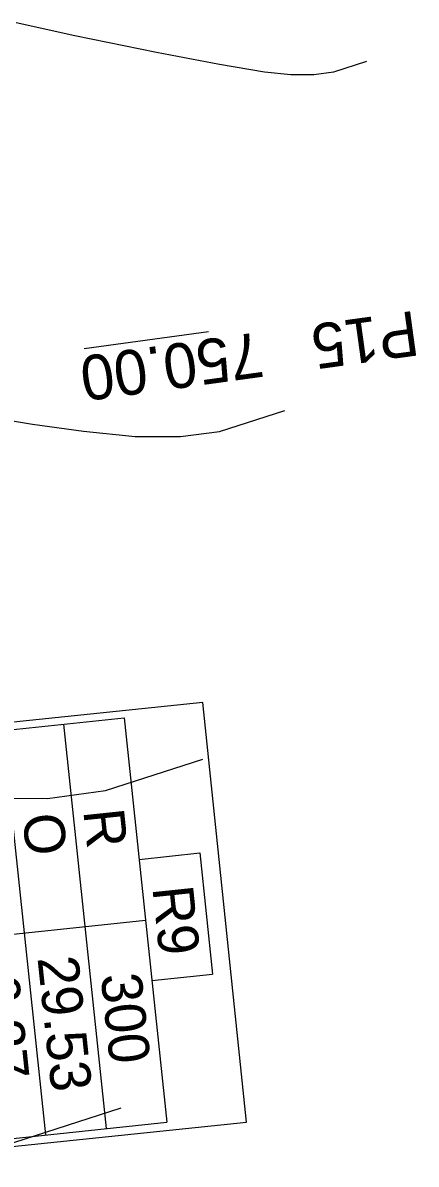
# Model space of a CAD drawing. Extents: x -574342 to -507939, y -1144044 to -1123894.
# Drawn here: x -508524.7 to -508502.7, y -1143810.6 to -1143746.9 of the extents above; entities that cross this region are included whole.
import ezdxf

# ---------------------------------------------------------------- set-up
doc = ezdxf.new("R2010")
doc.units = 0
for name, color, linetype in [('19', 7, 'Continuous'), ('6', 7, 'Continuous'), ('SO 101_popis oblouku', 7, 'Continuous'), ('VRST HL', 7, 'Continuous'), ('VRST VEDL', 7, 'Continuous')]:
    doc.layers.add(name, color=color, linetype=linetype)

msp = doc.modelspace()

# ---------------------------------------------------------------- linework, layer by layer
msp.add_lwpolyline([(-508536.292, -1143787.057), (-508533.867, -1143810.452), (-508512.21, -1143808.207), (-508514.636, -1143784.812)], close=True)
at = {"layer": '6'}
msp.add_lwpolyline([(-508514.323, -1143764.137), (-508521.258, -1143765.091)], dxfattribs=at)
at = {"layer": 'SO 101_popis oblouku'}
for p, q in [((-508535.931, -1143787.457), (-508519.025, -1143785.668)), ((-508519.025, -1143785.668), (-508516.64, -1143808.209)), ((-508525.787, -1143786.384), (-508523.403, -1143808.925)), ((-508522.406, -1143786.026), (-508520.022, -1143808.567)), ((-508518.19, -1143793.558), (-508514.809, -1143793.2)), ((-508514.809, -1143793.2), (-508514.094, -1143799.962)), ((-508534.738, -1143798.727), (-508517.833, -1143796.939)), ((-508517.475, -1143800.32), (-508514.094, -1143799.962)), ((-508533.546, -1143809.998), (-508516.64, -1143808.209))]:
    msp.add_line(p, q, dxfattribs=at)
at = {"layer": 'VRST HL'}
msp.add_lwpolyline([(-508519.201, -1143807.428), (-508526.409, -1143809.757), (-508529.856, -1143810.424), (-508533.145, -1143810.594), (-508536.278, -1143810.268), (-508538.531, -1143810.051), (-508539.907, -1143809.943), (-508540.403, -1143809.945), (-508540.962, -1143809.953), (-508541.582, -1143809.966), (-508542.265, -1143809.984), (-508542.825, -1143810.047), (-508543.263, -1143810.156), (-508543.579, -1143810.31), (-508543.802, -1143810.429), (-508543.932, -1143810.515), (-508543.97, -1143810.565)], dxfattribs=at)
at = {"layer": 'VRST VEDL'}
for points in [[(-508505.51, -1143749.067), (-508507.353, -1143749.662), (-508508.455, -1143749.81), (-508509.739, -1143749.807), (-508511.205, -1143749.654), (-508513.7, -1143749.241), (-508517.224, -1143748.567), (-508521.777, -1143747.633), (-508525.033, -1143746.912)], [(-508526.914, -1143768.817), (-508524.132, -1143769.29), (-508521.297, -1143769.678), (-508518.409, -1143769.979), (-508515.878, -1143769.984), (-508513.705, -1143769.694), (-508510.074, -1143768.521)], [(-508527.078, -1143790.151), (-508523.3, -1143790.159), (-508520.057, -1143789.725), (-508514.637, -1143787.975)]]:
    msp.add_lwpolyline(points, dxfattribs=at)

# ---------------------------------------------------------------- texts
at = {"layer": '19'}
msp.add_text('P15   750.00', height=2.5, rotation=187.83426, dxfattribs=at).set_placement((-508502.815, -1143762.957))
at = {"layer": 'SO 101_popis oblouku'}
for s, height, p in [('O', 2.267, (-508524.697, -1143791.098)), ('R', 2.267, (-508521.304, -1143790.848)), ('R9', 2.2667, (-508517.453, -1143795.14)), ('29.53', 2.2667, (-508523.855, -1143799.054)), ('300', 2.2667, (-508520.335, -1143800.011)), ('6.27', 2.2667, (-508527.166, -1143800.077))]:
    msp.add_text(s, height=height, rotation=276.03377, dxfattribs=at).set_placement(p)

doc.saveas('drawing.dxf')
